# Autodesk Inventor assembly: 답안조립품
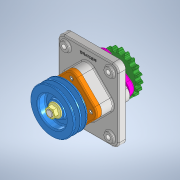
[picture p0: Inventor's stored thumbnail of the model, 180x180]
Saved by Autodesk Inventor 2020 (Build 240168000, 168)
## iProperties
Created: 2021-07
Part Number: 답안조립품
Document SubType Name: Assembly
Designer: Owner
Author: Owner
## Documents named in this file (16)
- C:\Users\Owner\Desktop\710707V1011\답안조립품.iam
- C:\Users\Owner\Desktop\710707V1011\본체.ipt
- C:\Users\Owner\Desktop\710707V1011\M16 너트.ipt
- C:\Users\Owner\Desktop\710707V1011\V-벨트풀리.ipt
- C:\Users\Owner\Desktop\710707V1011\멈춤나사 M4.ipt
- C:\Users\Owner\Desktop\710707V1011\베어링 6206.ipt
- C:\Users\Owner\Desktop\710707V1011\볼트 M6.ipt
- C:\Users\Owner\Desktop\710707V1011\부시.ipt
- C:\Users\Owner\Desktop\710707V1011\오일실 30x42x8.ipt
- C:\Users\Owner\Desktop\710707V1011\오일실 30x45x8.ipt
- C:\Users\Owner\Desktop\710707V1011\체인 스프로킷.ipt
- C:\Users\Owner\Desktop\710707V1011\축.ipt
- C:\Users\Owner\Desktop\710707V1011\커버A.ipt
- C:\Users\Owner\Desktop\710707V1011\커버B.ipt
- C:\Users\Owner\Desktop\710707V1011\키 6x6x18.ipt
- C:\Users\Owner\Desktop\710707V1011\키 6x6x20.ipt
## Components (3 placed, 2 different names)
1. M16 너트:1
2. V-벨트풀리:1 — 각도:1
3. M16 너트:2
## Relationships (1: Angle 1)
- 각도:1 [Angle]: V-벨트풀리:1
